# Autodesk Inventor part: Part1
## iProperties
Shininess: 64.0
Length Units: 11269
Angle Units: 11279
Time Units: 11290
Mass Units: 11283
Length Display Precision: 3
Angle Display Precision: 2
Compacted: True
Part Number: Part1
Document SubType Name: Modeling
Created: 2003-08
Designer: Owner
Manufacturer: Standard
Standards Organization: Custom
Density: 0.0
Volumn: 0.0
Area: 0.0
PropertySet Name: Model Information
Control State: 0
Master: False
Checked Out: False
Author: Owner
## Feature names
1. Split6
2. Split7
